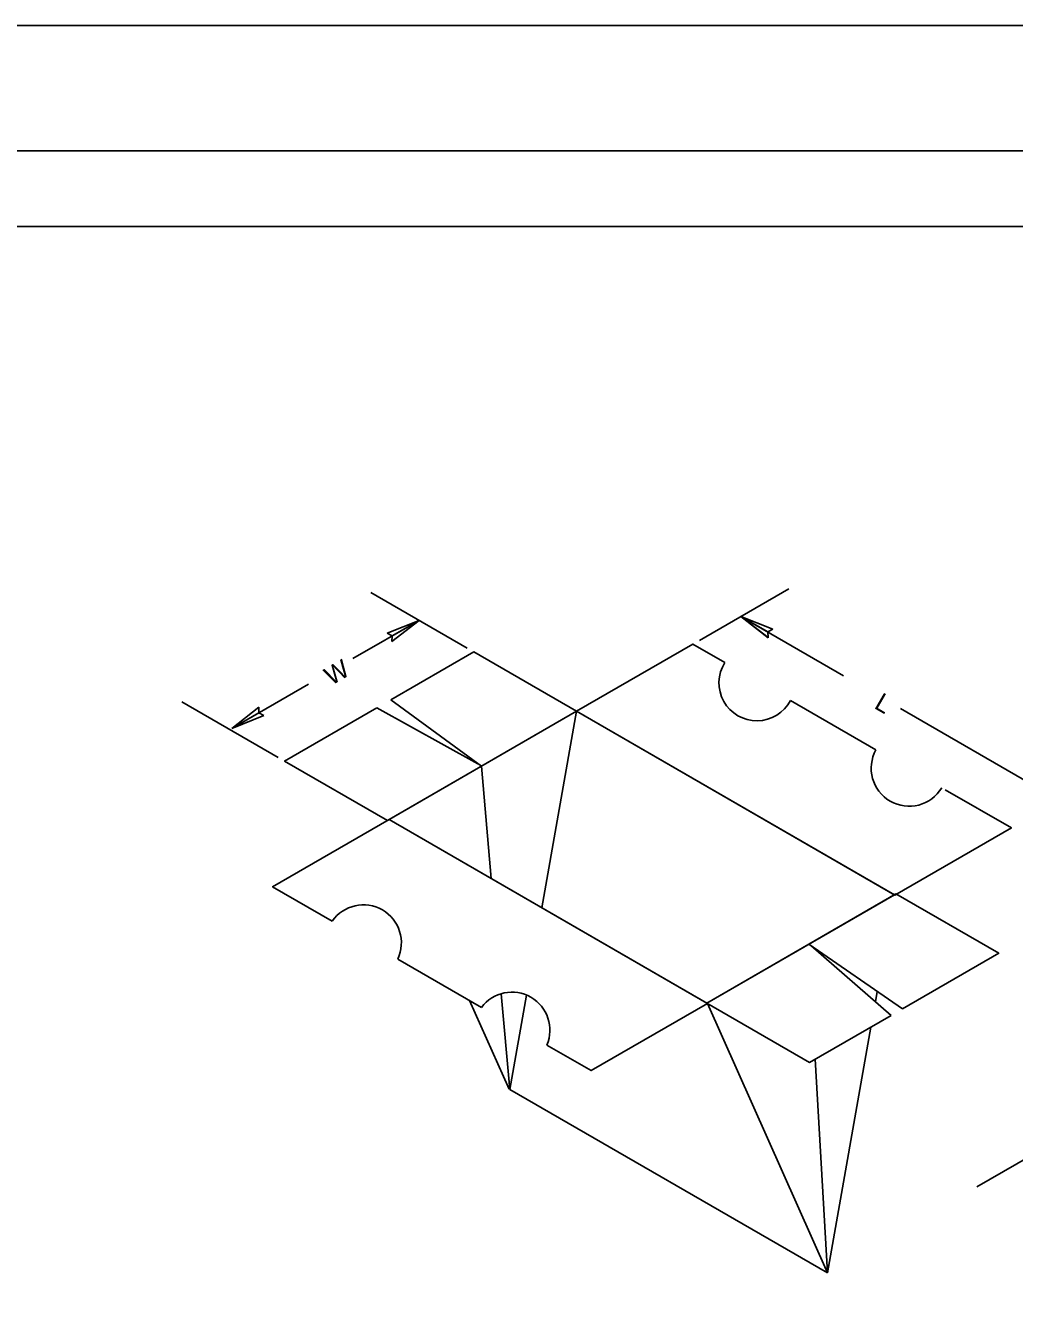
# Model space of a CAD drawing. Extents: x -120.7 to -50.3, y -20.2 to 3.8.
# Drawn here: x -61.42 to -54.91, y -4.59 to 3.76 of the extents above; entities that cross this region are included whole.
import ezdxf

# ---------------------------------------------------------------- set-up
doc = ezdxf.new("R2010")
doc.units = 0
for name, color, linetype in [('5', 7, 'Continuous'), ('Default', 7, 'Continuous'), ('PR_Dimensions', 7, 'Continuous'), ('SHT_Plot_Shape_Full', 7, 'Continuous'), ('SHT_Plot_Shape_Half', 7, 'Continuous'), ('SHT_Sheet_Border', 7, 'Continuous'), ('TYP_Typical_Section_Linework', 7, 'Continuous'), ('TYP_Typical_Section_Txt', 7, 'Continuous')]:
    doc.layers.add(name, color=color, linetype=linetype)

# ---------------------------------------------------------------- blocks, each defined once
blk = doc.blocks.new('AR32_1')
at = {"layer": 'Default'}
for p, q in [((0, 0), (-11.43, 1.6)), ((-11.43, 1.6), (-10.39, -0.01)), ((-11.42, -1.63), (0, 0)), ((-10.39, -0.01), (-11.42, -1.63))]:
    blk.add_line(p, q, dxfattribs=at)

msp = doc.modelspace()

# ---------------------------------------------------------------- linework, layer by layer
at = {"layer": '5'}
msp.add_line((-55.8155, -2.6008), (-55.8275, -2.669), dxfattribs=at)
at = {"layer": 'PR_Dimensions'}
for p, q in [((-59.1488, 0.0248), (-58.5151, -0.3411)), ((-56.3974, 0.0499), (-56.9856, -0.2898)), ((-58.8319, -0.1581), (-59.2687, -0.4103)), ((-58.8319, -0.1581), (-59.0424, -0.2434)), ((-59.0106, -0.2983), (-58.8319, -0.1581)), ((-58.8319, -0.1581), (-59.0089, -0.2607)), ((-58.8319, -0.1581), (-58.8319, -0.1581)), ((-58.8319, -0.1581), (-58.8319, -0.1581)), ((-56.7131, -0.1324), (-56.0369, -0.5229)), ((-56.5024, -0.2171), (-56.7131, -0.1324)), ((-56.7131, -0.1324), (-56.536, -0.2347)), ((-56.536, -0.2347), (-56.7131, -0.1324)), ((-56.7131, -0.1324), (-56.534, -0.2721)), ((-59.0424, -0.2434), (-59.0092, -0.2605)), ((-56.5358, -0.2348), (-56.536, -0.2347)), ((-56.5358, -0.2344), (-56.5024, -0.2171)), ((-56.534, -0.2721), (-56.5358, -0.2348)), ((-59.0089, -0.2607), (-59.0106, -0.2983)), ((-59.5588, -0.5778), (-60.0642, -0.8696)), ((-59.7601, -1.0599), (-60.3938, -0.694)), ((-59.8855, -0.7294), (-60.0642, -0.8696)), ((-59.8872, -0.7671), (-59.8855, -0.7294)), ((-55.6619, -0.7393), (-54.6173, -1.3424)), ((-60.0642, -0.8696), (-59.8871, -0.7673)), ((-60.0642, -0.8696), (-59.8537, -0.7843)), ((-59.8537, -0.7843), (-59.8869, -0.7672)), ((-54.0005, -3.2181), (-55.1594, -3.8871))]:
    msp.add_line(p, q, dxfattribs=at)
for points in [[(-59.0092, -0.2605), (-59.0091, -0.2604), (-58.8319, -0.1581)], [(-56.536, -0.2347), (-56.5358, -0.2344)], [(-59.8869, -0.7672), (-59.8871, -0.7673), (-60.0642, -0.8696)], [(-59.8871, -0.7673), (-59.8872, -0.7671)]]:
    msp.add_lwpolyline(points, dxfattribs=at)
at = {"layer": 'SHT_Plot_Shape_Full'}
msp.add_lwpolyline([(-86.2592, 3.7586), (-50.2592, 3.7586), (-50.2592, -20.2414), (-86.2592, -20.2414)], close=True, dxfattribs=at)
at = {"layer": 'SHT_Plot_Shape_Half'}
msp.add_lwpolyline([(-84.6217, 2.9337), (-50.6217, 2.9337), (-50.6217, -19.0663), (-84.6217, -19.0663)], close=True, dxfattribs=at)
at = {"layer": 'SHT_Sheet_Border'}
msp.add_lwpolyline([(-51.1717, -18.5663), (-82.6717, -18.5663), (-82.6717, 2.4337), (-51.1717, 2.4337)], close=True, dxfattribs=at)
at = {"layer": 'TYP_Typical_Section_Linework'}
for p, q in [((-59.1093, -0.7341), (-58.4444, -1.1022)), ((-59.0181, -0.6815), (-58.4217, -1.1189)), ((-56.3864, -0.6858), (-55.8242, -1.0103)), ((-57.7948, -0.7569), (-58.0236, -2.0505)), ((-58.4217, -1.1189), (-58.3568, -1.8582)), ((-55.649, -2.7152), (-56.2671, -2.2904)), ((-55.7242, -2.7586), (-56.2539, -2.2994)), ((-58.4204, -2.7058), (-58.9717, -2.3875)), ((-58.4989, -2.6605), (-58.239, -3.2435)), ((-58.2904, -2.6158), (-58.2351, -3.2457)), ((-58.1252, -2.6246), (-58.2351, -3.2457)), ((-56.9337, -2.6798), (-56.1432, -4.4535)), ((-55.857, -2.8353), (-56.1432, -4.4535)), ((-56.2238, -3.0471), (-56.1432, -4.4535)), ((-58.2351, -3.2458), (-56.1432, -4.4535))]:
    msp.add_line(p, q, dxfattribs=at)
for points in [[(-55.3696, -1.2728), (-54.9331, -1.5248), (-55.699, -1.9669), (-57.7948, -0.7569), (-57.0289, -0.3148), (-56.8191, -0.4359)], [(-59.0181, -0.6815), (-58.4718, -0.3661), (-57.7948, -0.7569), (-59.0398, -1.4757), (-59.7168, -1.0849), (-59.1093, -0.7341)], [(-59.0295, -1.4698), (-57.7948, -0.7569), (-55.7029, -1.9646), (-56.9377, -2.6775), (-59.0295, -1.4698)], [(-59.4032, -2.1384), (-59.7954, -1.9119), (-59.0295, -1.4698), (-56.9337, -2.6798), (-57.6996, -3.122), (-57.9905, -2.954)], [(-55.7242, -2.7586), (-56.2607, -3.0684), (-56.9377, -2.6775), (-55.6926, -1.9587), (-55.0156, -2.3495), (-55.649, -2.7152)]]:
    msp.add_lwpolyline(points, dxfattribs=at)
for centre, start, end in [((-56.6076, -0.5692), 147.77861, 332.22088), ((-55.6056, -1.1317), 150.9565, 329.04343), ((-59.198, -2.2811), 334.81291, 145.18702), ((-58.2204, -2.8558), 336.87317, 143.12676)]:
    msp.add_arc(centre, 0.25, start, end, dxfattribs=at)

# ---------------------------------------------------------------- block references
at = {"layer": 'PR_Dimensions'}
for p, xscale, yscale, rotation in [((-58.8319, -0.1581), 0.019685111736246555, 0.019685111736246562, 29.99993546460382), ((-56.7131, -0.1324), 0.019685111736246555, 0.019685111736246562, 150.00006453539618), ((-60.0642, -0.8696), 0.019685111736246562, 0.019685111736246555, -150.0000645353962)]:
    msp.add_blockref('AR32_1', p, dxfattribs=dict(at, xscale=xscale, yscale=yscale, rotation=rotation))

# ---------------------------------------------------------------- texts
at = {"layer": 'TYP_Typical_Section_Txt'}
for s, rotation, p in [('W', 29.99997, (-59.4096, -0.5896)), ('L', 329.99996, (-55.8425, -0.7331))]:
    msp.add_text(s, height=0.12, rotation=rotation, dxfattribs=at).set_placement(p)

doc.saveas('drawing.dxf')
